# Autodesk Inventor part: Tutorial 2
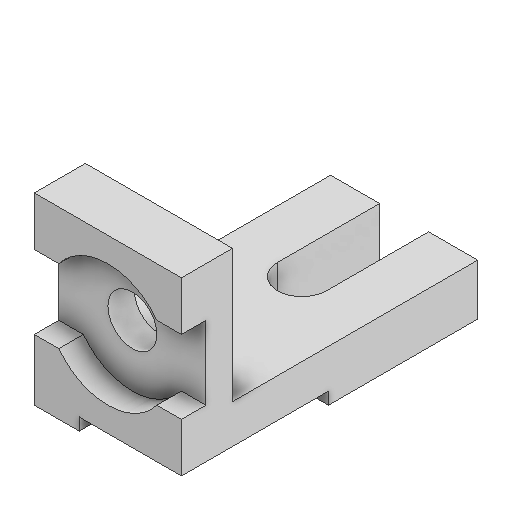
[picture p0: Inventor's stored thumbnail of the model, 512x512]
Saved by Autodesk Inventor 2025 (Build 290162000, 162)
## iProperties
Created: 2021-03
Part Number: Tutorial 2
Material: Generic
Document SubType Name: Modeling
Designer: ASUS Laptop
Density: 1 g/cm^3
Appearance: Default
Author: ASUS Laptop
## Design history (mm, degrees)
sketch "Sketch1"
  geometry: L1 (0, 0)-(90, 0); L2 (90, 0)-(90, -25); L3 (90, -25)-(25, -25); L4 (25, -25)-(25, -145); L5 (25, -145)-(0, -145); L6 (0, -145)-(0, 0)
  constraints: 12 end point, 6 perpendicular, 1 horizontal
  dimensions: "d0" = 145 distance of L5.end L1.start; "d1" = 90 distance between parallel lines of L2 L6; "d2" = 25 distance of L1.end L2.end
extrude "Extrusion1" new body sketch "Sketch1" stored distance "d4" = 72; taper "d5" = 0 deg
sketch "Sketch2"
  geometry: L1 (0, 0)-(72, 0); L2 (72, 0)-(72, 6); L3 (72, 6)-(0, 6); L4 (0, 6)-(0, 0)
  constraints: 8 end point, 2 parallel, 1 horizontal, 1 perpendicular
  dimensions: "d6" = 72 distance of L1.start L1.end; "d7" = 6 distance between parallel lines of L1 L3
extrude "Extrusion2" cut sketch "Sketch2" distance "d8" = 50; taper "d9" = 0 deg
sketch "Sketch3"
  geometry: L1 (12, -24)-(0, -24); L2 (0, -90)-(0, 0) reference; L3 (0, -24)-(0, -60); L4 (0, -60)-(12, -60); L5 (60, -24)-(72, -24); L6 (72, 0)-(72, -84) reference; L7 (72, -24)-(72, -60); L8 (72, -60)-(60, -60); L9 (72, -90)-(22, -90) reference; L10 (0, -90)-(22, -90) reference; A1 r 30 centre (36, -42) between (12, -60) and (60, -60); A2 r 30 centre (36, -42) between (60, -24) and (12, -24); 3 further points
  constraints: 12 end point, 4 point on circle, 4 point on line, 2 centre point, 2 perpendicular, 1 collinear, 1 concentric, 1 horizontal, 1 parallel, 1 vertical
  dimensions: "d10" = 30 radius of A2; "d11" = 36 distance from line of A1.centre L2; "d12" = 48 distance from line of L9 A1.centre; "d13" = 30 distance between parallel lines of L4 L10; "d14" = 36 distance between parallel lines of L4 L1
extrude "Extrusion3" cut sketch "Sketch3" distance "d15" = 12; taper "d16" = 0 deg
sketch "Sketch4"
  geometry: C1 r 12 at (36, -42); A1 r 30 centre (36, -42) between (60, -24) and (12, -24) reference; 1 further point
  constraints: 1 centre point, 1 concentric
  dimensions: "d17" = 24 diameter of C1
extrude "Extrusion4" cut sketch "Sketch4" extent not by distance; stored distance "d18" = 10; taper "d19" = 0 deg
sketch "Sketch5"
  geometry: L1 (24, 120)-(24, 70); L2 (48, 70)-(48, 120); L3 (48, 120)-(24, 120); L4 (72, 120)-(72, 0) reference; A1 r 12 centre (36, 70) between (24, 70) and (48, 70); 2 further points
  constraints: 6 end point, 2 point on circle, 2 tangent, 1 centre point, 1 parallel, 1 perpendicular, 1 point on line, 1 vertical
  dimensions: "d20" = 36 distance from line of A1.centre L4; "d21" = 12 radius of A1; "d22" = 50 distance of L2.start L2.end
extrude "Extrusion5" cut sketch "Sketch5" extent not by distance; stored distance "d23" = 0; taper "d24" = 0 deg
body "Solid1"
